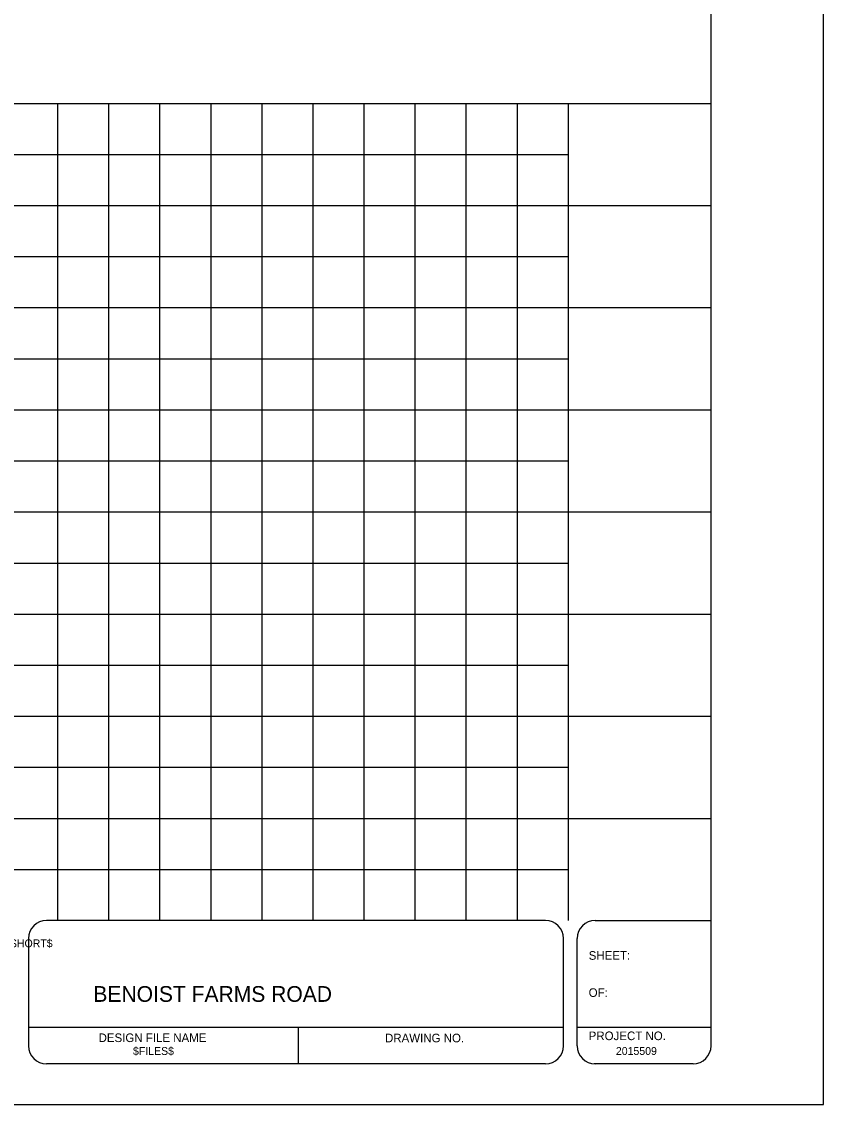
# Model space of a CAD drawing. Extents: x -4 to 16, y -3 to 9.7.
# Drawn here: x 12.02 to 15.95, y -0.9 to 4.4 of the extents above; entities that cross this region are included whole.
import ezdxf

# ---------------------------------------------------------------- set-up
doc = ezdxf.new("R2010")
doc.units = 0
for name, color, linetype in [('Baseline Bearing and Curve Data', 7, 'Continuous'), ('Baseline Station and Tick Mark', 7, 'Continuous'), ('Centerline (Construction)', 7, 'Continuous'), ('Default', 7, 'Continuous'), ('Property Corners', 7, 'Continuous')]:
    doc.layers.add(name, color=color, linetype=linetype)

msp = doc.modelspace()

# ---------------------------------------------------------------- linework, layer by layer
at = {"layer": 'Baseline Bearing and Curve Data'}
for p, q in [((12.2, 4), (12.2, 0)), ((12.7, 4), (12.7, 0)), ((13.2, 4), (13.2, 0)), ((13.7, 4), (13.7, 0)), ((14.2, 4), (14.2, 0)), ((14.7, 4), (14.7, 0)), ((0, 3.5), (15.4, 3.5)), ((0, 3), (15.4, 3)), ((0, 2.5), (15.4, 2.5)), ((0, 2), (15.4, 2)), ((0, 1.5), (15.4, 1.5)), ((0, 1), (15.4, 1)), ((0, 0.5), (15.4, 0.5))]:
    msp.add_line(p, q, dxfattribs=at)
at = {"layer": 'Baseline Station and Tick Mark'}
msp.add_line((0, 4), (15.4, 4), dxfattribs=at)
at = {"layer": 'Centerline (Construction)'}
msp.add_lwpolyline([(-0.55, -0.9), (15.95, -0.9), (15.95, 9.7), (-0.55, 9.7)], close=True, dxfattribs=at)
at = {"layer": 'Default'}
for p, q in [((15.4, -0.6133), (15.4, 9.5065)), ((14.5898, 0), (12.146, 0)), ((14.8324, 0), (15.4, 0)), ((12.0578, -0.0882), (12.0578, -0.6131)), ((14.678, -0.6135), (14.678, -0.0884)), ((14.7442, -0.6135), (14.7442, -0.0884)), ((14.6769, -0.5241), (12.0568, -0.5241)), ((13.3801, -0.7005), (13.3801, -0.5241)), ((15.4, -0.5241), (14.7475, -0.5241)), ((14.5898, -0.7014), (12.146, -0.7014)), ((15.3118, -0.7015), (14.8271, -0.7015))]:
    msp.add_line(p, q, dxfattribs=at)
for centre, major_axis, start_param, end_param in [((12.146, -0.0882), (0, 0.0882), 0, 1.570796), ((14.5898, -0.0884), (0, 0.0882), 4.712389, 6.283185), ((14.8324, -0.0884), (0, -0.0882), 3.141593, 4.712389), ((12.146, -0.6131), (0, -0.0882), 4.712389, 6.283185), ((14.5898, -0.6131), (0, 0.0882), 3.141593, 4.712389), ((14.8324, -0.6135), (0, -0.0882), 4.712389, 6.283185), ((15.3118, -0.6133), (0, -0.0882), 0, 1.570796)]:
    msp.add_ellipse(centre, major_axis=major_axis, ratio=0.999927, start_param=start_param, end_param=end_param, dxfattribs=at)
at = {"layer": 'Property Corners'}
for p, q in [((12.45, 4), (12.45, 0)), ((12.95, 4), (12.95, 0)), ((13.45, 4), (13.45, 0)), ((13.95, 4), (13.95, 0)), ((14.45, 4), (14.45, 0)), ((0.7, 3.75), (14.7, 3.75)), ((0.7, 3.25), (14.7, 3.25)), ((0.7, 2.75), (14.7, 2.75)), ((0.7, 2.25), (14.7, 2.25)), ((0.7, 1.75), (14.7, 1.75)), ((0.7, 1.25), (14.7, 1.25)), ((0.7, 0.75), (14.7, 0.75)), ((0.7, 0.25), (14.7, 0.25))]:
    msp.add_line(p, q, dxfattribs=at)

# ---------------------------------------------------------------- texts
at = {"layer": 'Default'}
for s, height, p in [('$SCALESHORT$', 0.038546, (11.7691, -0.1311)), ('SHEET:', 0.04207, (14.8009, -0.1922)), ('   BENOIST FARMS ROAD   ', 0.077091, (12.2895, -0.3982)), ('OF:', 0.04207, (14.8009, -0.374)), ('DESIGN FILE NAME', 0.042066, (12.4009, -0.5951)), ('DRAWING NO.', 0.042066, (13.8035, -0.5964)), ('PROJECT NO.', 0.042066, (14.8009, -0.5856)), ('$FILES$', 0.03855, (12.5694, -0.6581)), ('2015509', 0.03855, (14.9341, -0.6581))]:
    msp.add_text(s, height=height, dxfattribs=at).set_placement(p)

doc.saveas('drawing.dxf')
